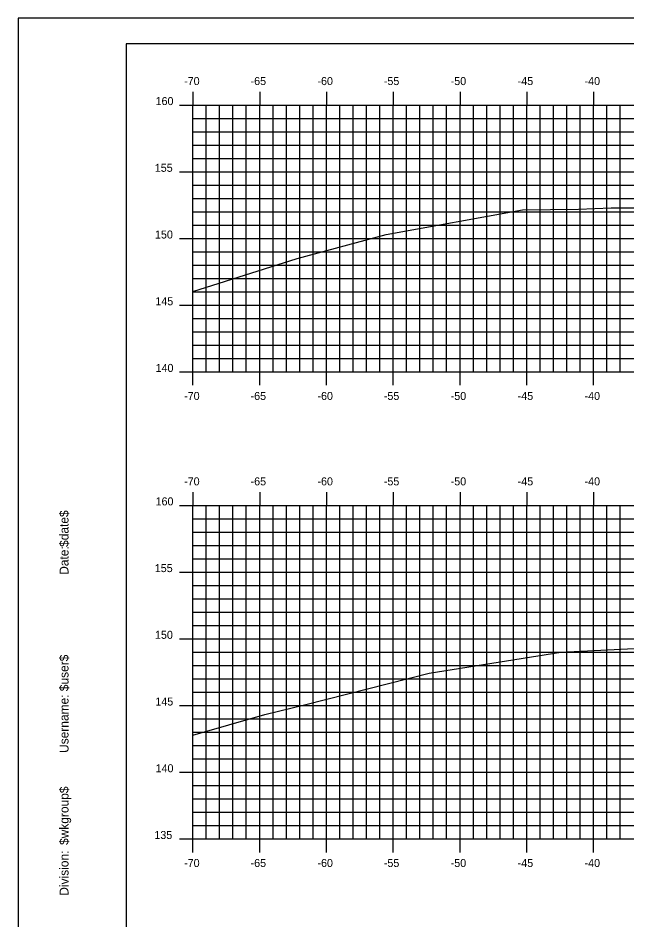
# Model space of a CAD drawing. Extents: x 852082 to 852254, y 365876 to 365986.
# Drawn here: x 852082.1 to 852127.7, y 365918.2 to 365985.8 of the extents above; entities that cross this region are included whole.
import ezdxf

# ---------------------------------------------------------------- set-up
doc = ezdxf.new("R2010")
doc.units = 0
for name, color, linetype in [('BORDER', 7, 'Continuous'), ('H_V ANNOTATION', 7, 'Continuous'), ('MAJOR', 7, 'Continuous'), ('MINOR', 7, 'Continuous'), ('PLOT BOUNDARY', 7, 'Continuous'), ('S_Roadway_Centerline', 7, 'Continuous')]:
    doc.layers.add(name, color=color, linetype=linetype)

msp = doc.modelspace()

# ---------------------------------------------------------------- linework, layer by layer
at = {"layer": 'BORDER'}
msp.add_lwpolyline([(852090.168, 365878.833), (852250.168, 365878.833), (852250.168, 365983.833), (852090.168, 365983.833)], close=True, dxfattribs=at)
at = {"layer": 'MAJOR'}
for p, q in [((852095.168, 365980.253), (852095.168, 365979.251)), ((852100.168, 365980.253), (852100.168, 365979.251)), ((852105.168, 365980.253), (852105.168, 365979.251)), ((852110.168, 365980.253), (852110.168, 365979.251)), ((852115.168, 365980.253), (852115.168, 365979.251)), ((852120.168, 365980.253), (852120.168, 365979.251)), ((852125.168, 365980.253), (852125.168, 365979.251)), ((852094.166, 365979.251), (852095.168, 365979.251)), ((852095.168, 365979.251), (852235.168, 365979.251)), ((852095.168, 365959.251), (852095.168, 365979.251)), ((852095.168, 365959.251), (852095.168, 365979.251)), ((852095.168, 365979.251), (852235.168, 365979.251)), ((852100.168, 365959.251), (852100.168, 365979.251)), ((852105.168, 365959.251), (852105.168, 365979.251)), ((852110.168, 365959.251), (852110.168, 365979.251)), ((852115.168, 365959.251), (852115.168, 365979.251)), ((852120.168, 365959.251), (852120.168, 365979.251)), ((852125.168, 365959.251), (852125.168, 365979.251)), ((852094.166, 365974.251), (852095.168, 365974.251)), ((852095.168, 365974.251), (852235.168, 365974.251)), ((852094.166, 365969.251), (852095.168, 365969.251)), ((852095.168, 365969.251), (852235.168, 365969.251)), ((852094.166, 365964.251), (852095.168, 365964.251)), ((852095.168, 365964.251), (852235.168, 365964.251)), ((852094.166, 365959.251), (852095.168, 365959.251)), ((852095.168, 365959.251), (852235.168, 365959.251)), ((852095.168, 365959.251), (852235.168, 365959.251)), ((852095.168, 365958.249), (852095.168, 365959.251)), ((852100.168, 365958.249), (852100.168, 365959.251)), ((852105.168, 365958.249), (852105.168, 365959.251)), ((852110.168, 365958.249), (852110.168, 365959.251)), ((852115.168, 365958.249), (852115.168, 365959.251)), ((852120.168, 365958.249), (852120.168, 365959.251)), ((852125.168, 365958.249), (852125.168, 365959.251)), ((852095.168, 365950.253), (852095.168, 365949.251)), ((852100.168, 365950.253), (852100.168, 365949.251)), ((852105.168, 365950.253), (852105.168, 365949.251)), ((852110.168, 365950.253), (852110.168, 365949.251)), ((852115.168, 365950.253), (852115.168, 365949.251)), ((852120.168, 365950.253), (852120.168, 365949.251)), ((852125.168, 365950.253), (852125.168, 365949.251)), ((852094.166, 365949.251), (852095.168, 365949.251)), ((852095.168, 365949.251), (852235.168, 365949.251)), ((852095.168, 365924.251), (852095.168, 365949.251)), ((852095.168, 365924.251), (852095.168, 365949.251)), ((852095.168, 365949.251), (852235.168, 365949.251)), ((852100.168, 365924.251), (852100.168, 365949.251)), ((852105.168, 365924.251), (852105.168, 365949.251)), ((852110.168, 365924.251), (852110.168, 365949.251)), ((852115.168, 365924.251), (852115.168, 365949.251)), ((852120.168, 365924.251), (852120.168, 365949.251)), ((852125.168, 365924.251), (852125.168, 365949.251)), ((852094.166, 365944.251), (852095.168, 365944.251)), ((852095.168, 365944.251), (852235.168, 365944.251)), ((852094.166, 365939.251), (852095.168, 365939.251)), ((852095.168, 365939.251), (852235.168, 365939.251)), ((852094.166, 365934.251), (852095.168, 365934.251)), ((852095.168, 365934.251), (852235.168, 365934.251)), ((852094.166, 365929.251), (852095.168, 365929.251)), ((852095.168, 365929.251), (852235.168, 365929.251)), ((852094.166, 365924.251), (852095.168, 365924.251)), ((852095.168, 365924.251), (852235.168, 365924.251)), ((852095.168, 365924.251), (852235.168, 365924.251)), ((852095.168, 365923.249), (852095.168, 365924.251)), ((852100.168, 365923.249), (852100.168, 365924.251)), ((852105.168, 365923.249), (852105.168, 365924.251)), ((852110.168, 365923.249), (852110.168, 365924.251)), ((852115.168, 365923.249), (852115.168, 365924.251)), ((852120.168, 365923.249), (852120.168, 365924.251)), ((852125.168, 365923.249), (852125.168, 365924.251))]:
    msp.add_line(p, q, dxfattribs=at)
at = {"layer": 'MINOR'}
for p, q in [((852096.168, 365959.251), (852096.168, 365979.251)), ((852097.168, 365959.251), (852097.168, 365979.251)), ((852098.168, 365959.251), (852098.168, 365979.251)), ((852099.168, 365959.251), (852099.168, 365979.251)), ((852101.168, 365959.251), (852101.168, 365979.251)), ((852102.168, 365959.251), (852102.168, 365979.251)), ((852103.168, 365959.251), (852103.168, 365979.251)), ((852104.168, 365959.251), (852104.168, 365979.251)), ((852106.168, 365959.251), (852106.168, 365979.251)), ((852107.168, 365959.251), (852107.168, 365979.251)), ((852108.168, 365959.251), (852108.168, 365979.251)), ((852109.168, 365959.251), (852109.168, 365979.251)), ((852111.168, 365959.251), (852111.168, 365979.251)), ((852112.168, 365959.251), (852112.168, 365979.251)), ((852113.168, 365959.251), (852113.168, 365979.251)), ((852114.168, 365959.251), (852114.168, 365979.251)), ((852116.168, 365959.251), (852116.168, 365979.251)), ((852117.168, 365959.251), (852117.168, 365979.251)), ((852118.168, 365959.251), (852118.168, 365979.251)), ((852119.168, 365959.251), (852119.168, 365979.251)), ((852121.168, 365959.251), (852121.168, 365979.251)), ((852122.168, 365959.251), (852122.168, 365979.251)), ((852123.168, 365959.251), (852123.168, 365979.251)), ((852124.168, 365959.251), (852124.168, 365979.251)), ((852126.168, 365959.251), (852126.168, 365979.251)), ((852127.168, 365959.251), (852127.168, 365979.251)), ((852095.168, 365978.251), (852235.168, 365978.251)), ((852095.168, 365978.251), (852096.17, 365978.251)), ((852095.168, 365977.251), (852235.168, 365977.251)), ((852095.168, 365977.251), (852096.17, 365977.251)), ((852095.168, 365976.251), (852235.168, 365976.251)), ((852095.168, 365976.251), (852096.17, 365976.251)), ((852095.168, 365975.251), (852235.168, 365975.251)), ((852095.168, 365975.251), (852096.17, 365975.251)), ((852095.168, 365973.251), (852235.168, 365973.251)), ((852095.168, 365973.251), (852096.17, 365973.251)), ((852095.168, 365972.251), (852235.168, 365972.251)), ((852095.168, 365972.251), (852096.17, 365972.251)), ((852095.168, 365971.251), (852235.168, 365971.251)), ((852095.168, 365971.251), (852096.17, 365971.251)), ((852095.168, 365970.251), (852235.168, 365970.251)), ((852095.168, 365970.251), (852096.17, 365970.251)), ((852095.168, 365968.251), (852235.168, 365968.251)), ((852095.168, 365968.251), (852096.17, 365968.251)), ((852095.168, 365967.251), (852235.168, 365967.251)), ((852095.168, 365967.251), (852096.17, 365967.251)), ((852095.168, 365966.251), (852235.168, 365966.251)), ((852095.168, 365966.251), (852096.17, 365966.251)), ((852095.168, 365965.251), (852235.168, 365965.251)), ((852095.168, 365965.251), (852096.17, 365965.251)), ((852095.168, 365963.251), (852235.168, 365963.251)), ((852095.168, 365963.251), (852096.17, 365963.251)), ((852095.168, 365962.251), (852235.168, 365962.251)), ((852095.168, 365962.251), (852096.17, 365962.251)), ((852095.168, 365961.251), (852235.168, 365961.251)), ((852095.168, 365961.251), (852096.17, 365961.251)), ((852095.168, 365960.251), (852235.168, 365960.251)), ((852095.168, 365960.251), (852096.17, 365960.251)), ((852096.168, 365924.251), (852096.168, 365949.251)), ((852097.168, 365924.251), (852097.168, 365949.251)), ((852098.168, 365924.251), (852098.168, 365949.251)), ((852099.168, 365924.251), (852099.168, 365949.251)), ((852101.168, 365924.251), (852101.168, 365949.251)), ((852102.168, 365924.251), (852102.168, 365949.251)), ((852103.168, 365924.251), (852103.168, 365949.251)), ((852104.168, 365924.251), (852104.168, 365949.251)), ((852106.168, 365924.251), (852106.168, 365949.251)), ((852107.168, 365924.251), (852107.168, 365949.251)), ((852108.168, 365924.251), (852108.168, 365949.251)), ((852109.168, 365924.251), (852109.168, 365949.251)), ((852111.168, 365924.251), (852111.168, 365949.251)), ((852112.168, 365924.251), (852112.168, 365949.251)), ((852113.168, 365924.251), (852113.168, 365949.251)), ((852114.168, 365924.251), (852114.168, 365949.251)), ((852116.168, 365924.251), (852116.168, 365949.251)), ((852117.168, 365924.251), (852117.168, 365949.251)), ((852118.168, 365924.251), (852118.168, 365949.251)), ((852119.168, 365924.251), (852119.168, 365949.251)), ((852121.168, 365924.251), (852121.168, 365949.251)), ((852122.168, 365924.251), (852122.168, 365949.251)), ((852123.168, 365924.251), (852123.168, 365949.251)), ((852124.168, 365924.251), (852124.168, 365949.251)), ((852126.168, 365924.251), (852126.168, 365949.251)), ((852127.168, 365924.251), (852127.168, 365949.251)), ((852095.168, 365948.251), (852235.168, 365948.251)), ((852095.168, 365948.251), (852096.17, 365948.251)), ((852095.168, 365947.251), (852235.168, 365947.251)), ((852095.168, 365947.251), (852096.17, 365947.251)), ((852095.168, 365946.251), (852235.168, 365946.251)), ((852095.168, 365946.251), (852096.17, 365946.251)), ((852095.168, 365945.251), (852235.168, 365945.251)), ((852095.168, 365945.251), (852096.17, 365945.251)), ((852095.168, 365943.251), (852235.168, 365943.251)), ((852095.168, 365943.251), (852096.17, 365943.251)), ((852095.168, 365942.251), (852235.168, 365942.251)), ((852095.168, 365942.251), (852096.17, 365942.251)), ((852095.168, 365941.251), (852235.168, 365941.251)), ((852095.168, 365941.251), (852096.17, 365941.251)), ((852095.168, 365940.251), (852235.168, 365940.251)), ((852095.168, 365940.251), (852096.17, 365940.251)), ((852095.168, 365938.251), (852235.168, 365938.251)), ((852095.168, 365938.251), (852096.17, 365938.251)), ((852095.168, 365937.251), (852235.168, 365937.251)), ((852095.168, 365937.251), (852096.17, 365937.251)), ((852095.168, 365936.251), (852235.168, 365936.251)), ((852095.168, 365936.251), (852096.17, 365936.251)), ((852095.168, 365935.251), (852235.168, 365935.251)), ((852095.168, 365935.251), (852096.17, 365935.251)), ((852095.168, 365933.251), (852235.168, 365933.251)), ((852095.168, 365933.251), (852096.17, 365933.251)), ((852095.168, 365932.251), (852235.168, 365932.251)), ((852095.168, 365932.251), (852096.17, 365932.251)), ((852095.168, 365931.251), (852235.168, 365931.251)), ((852095.168, 365931.251), (852096.17, 365931.251)), ((852095.168, 365930.251), (852235.168, 365930.251)), ((852095.168, 365930.251), (852096.17, 365930.251)), ((852095.168, 365928.251), (852235.168, 365928.251)), ((852095.168, 365928.251), (852096.17, 365928.251)), ((852095.168, 365927.251), (852235.168, 365927.251)), ((852095.168, 365927.251), (852096.17, 365927.251)), ((852095.168, 365926.251), (852235.168, 365926.251)), ((852095.168, 365926.251), (852096.17, 365926.251)), ((852095.168, 365925.251), (852235.168, 365925.251)), ((852095.168, 365925.251), (852096.17, 365925.251))]:
    msp.add_line(p, q, dxfattribs=at)
at = {"layer": 'PLOT BOUNDARY'}
msp.add_lwpolyline([(852082.075, 365875.774), (852252.075, 365875.774), (852252.075, 365985.774), (852082.075, 365985.774)], close=True, dxfattribs=at)
at = {"layer": 'S_Roadway_Centerline'}
for points in [[(852095.168, 365965.291), (852102.983, 365967.751), (852109.638, 365969.561), (852119.85, 365971.412), (852124.043, 365971.45), (852126.494, 365971.554), (852130.337, 365971.548), (852130.768, 365971.552), (852132.048, 365971.521), (852138.064, 365971.59), (852141.636, 365971.639), (852141.982, 365971.645), (852142.114, 365971.643), (852142.175, 365971.642), (852142.217, 365971.644), (852142.469, 365971.646), (852157.738, 365971.356), (852165.168, 365971.404), (852167.027, 365971.408), (852172.495, 365971.458), (852180.691, 365971.651)], [(852095.168, 365932.035), (852100.557, 365933.57), (852103.621, 365934.329), (852112.858, 365936.686), (852122.724, 365938.245), (852129.21, 365938.577), (852133.162, 365938.801), (852142.098, 365939.382), (852143.386, 365939.369), (852155.914, 365939.169), (852161.169, 365939.088), (852162.204, 365939.089), (852165.106, 365939.013), (852169.996, 365938.978), (852179.789, 365938.46)]]:
    msp.add_lwpolyline(points, dxfattribs=at)

# ---------------------------------------------------------------- texts
at = {"layer": 'BORDER'}
for s, p in [('$date$', (852085.853, 365946.138)), ('Date:', (852085.853, 365944.05)), ('$user$', (852085.853, 365935.325)), ('Username:', (852085.853, 365930.701)), ('$wkgroup$', (852085.853, 365923.803)), ('Division:', (852085.853, 365919.999))]:
    msp.add_text(s, height=0.6696, rotation=90, dxfattribs=at).set_placement(p)
at = {"layer": 'H_V ANNOTATION'}
for s, p in [('-70', (852094.51, 365980.751)), ('-65', (852099.486, 365980.751)), ('-60', (852104.494, 365980.751)), ('-55', (852109.464, 365980.751)), ('-50', (852114.472, 365980.751)), ('-45', (852119.486, 365980.751)), ('-40', (852124.494, 365980.751)), ('160', (852092.373, 365979.251)), ('155', (852092.314, 365974.251)), ('150', (852092.33, 365969.251)), ('145', (852092.357, 365964.251)), ('140', (852092.373, 365959.251)), ('-70', (852094.51, 365957.151)), ('-65', (852099.486, 365957.151)), ('-60', (852104.494, 365957.151)), ('-55', (852109.464, 365957.151)), ('-50', (852114.472, 365957.151)), ('-45', (852119.486, 365957.151)), ('-40', (852124.494, 365957.151)), ('-70', (852094.51, 365950.751)), ('-65', (852099.486, 365950.751)), ('-60', (852104.494, 365950.751)), ('-55', (852109.464, 365950.751)), ('-50', (852114.472, 365950.751)), ('-45', (852119.486, 365950.751)), ('-40', (852124.494, 365950.751)), ('160', (852092.373, 365949.251)), ('155', (852092.314, 365944.251)), ('150', (852092.33, 365939.251)), ('145', (852092.357, 365934.251)), ('140', (852092.373, 365929.251)), ('135', (852092.282, 365924.251)), ('-70', (852094.51, 365922.151)), ('-65', (852099.486, 365922.151)), ('-60', (852104.494, 365922.151)), ('-55', (852109.464, 365922.151)), ('-50', (852114.472, 365922.151)), ('-45', (852119.486, 365922.151)), ('-40', (852124.494, 365922.151))]:
    msp.add_text(s, height=0.6, dxfattribs=at).set_placement(p)
at = {"layer": 'MAJOR'}
for p in [(852095.164, 365959.251), (852095.164, 365924.251)]:
    msp.add_text('-', height=0.006, dxfattribs=at).set_placement(p)

doc.saveas('drawing.dxf')
